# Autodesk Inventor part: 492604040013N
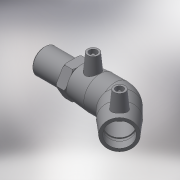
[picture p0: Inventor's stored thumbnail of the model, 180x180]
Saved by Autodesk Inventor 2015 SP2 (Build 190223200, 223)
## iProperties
Created: 2017-06
Part Number: 492604040013N
Material: Generic
Description: PLASSON 45° ELBOW TRANSITION MALE 40 x 1 1⁄4"
Document SubType Name: Modeling
Designer: KIM
Mass: 217.09 g
Surface Area: 532.812 cm^2
Volume: 217.09 cm^3
Density: 1 g/cm^3
Appearance: Default
Author: KIM
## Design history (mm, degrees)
derived "492604.ipt"
feature "Solid1::492604.ipt"
tag "TaggingFeature1"
body "Solid1"
other parameters: "d2" = 56, "d4" = 28.25, "d5" = 50.4, "d8" = 168 deg, "d10" = 19.2, "d11" = 6.4, "d29" = 47, "d30" = 15, "d31" = 39.55, "d34" = 5 deg, "d41" = 4, "d42" = 14, "d43" = 0, "d50" = 26, "d51" = 19.2, "d52" = 49.44, "d54" = 135 deg, "d86" = 25.2, "d87" = 135 deg, "d88" = 113, "d90" = 48, "d91" = 0, "d92" = 48, "d93" = 0, "d101" = 3, "d102" = 0, "d107" = 0.1, "d109" = 41.91, "d110" = 55, "d111" = 13.75, "d112" = 56, "d113" = 29.337, "d114" = 49.5, "d116" = 1.68, "d122" = 0, "d123" = 2.0955, "L_" = 168, "L_1" = 48, "A_" = 47, "d_2" = 12, "L_2" = 55, "R_" = 41.91, "D_1" = 56
